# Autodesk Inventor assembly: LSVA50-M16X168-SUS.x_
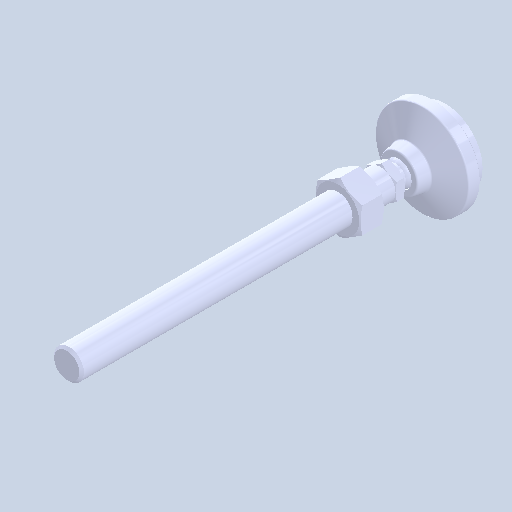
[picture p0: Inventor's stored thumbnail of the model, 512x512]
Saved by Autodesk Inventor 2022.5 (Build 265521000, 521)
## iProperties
Created: 2024-08
Part Number: LSVA50-M16X168-SUS.x_
Document SubType Name: Assembly
Designer: ImaoCorp
Author: ImaoCorp
Sending System: SOLIDWORKS 2022-2022290
MC: AMD64
MC_MODEL: Intel64 Family 6 Model 60 Stepping 3, GenuineIntel
OS: Windows_NT
FRU: Parasolid Version 33.1, build 260,  4-25-2022
FORMAT: text
GUISE: transmit
KEY: FILELSVA50-M16X168-SUS.x_t
DATE: Fri Aug 23 16:08:42 2024
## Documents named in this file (4)
- X:\14_SW2022-Inv2022\06_2024-10新製品(SME)\ELS_データ\l\lsva50-m16x168-sus\LSVA50-M16X168-SUS.x_.iam
- X:\14_SW2022-Inv2022\06_2024-10新製品(SME)\ELS_データ\l\lsva50-m16x168-sus\LSVA50-M16X168-SUS_01.ipt
- X:\14_SW2022-Inv2022\06_2024-10新製品(SME)\ELS_データ\l\lsva50-m16x168-sus\LSVA50-M16X168-SUS_02.ipt
- X:\14_SW2022-Inv2022\06_2024-10新製品(SME)\ELS_データ\l\lsva50-m16x168-sus\LSVA50-M16X168-SUS_03.ipt
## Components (3 placed, 3 different names)
1. LSVA50-M16X168-SUS_01
2. LSVA50-M16X168-SUS_02
3. LSVA50-M16X168-SUS_03
